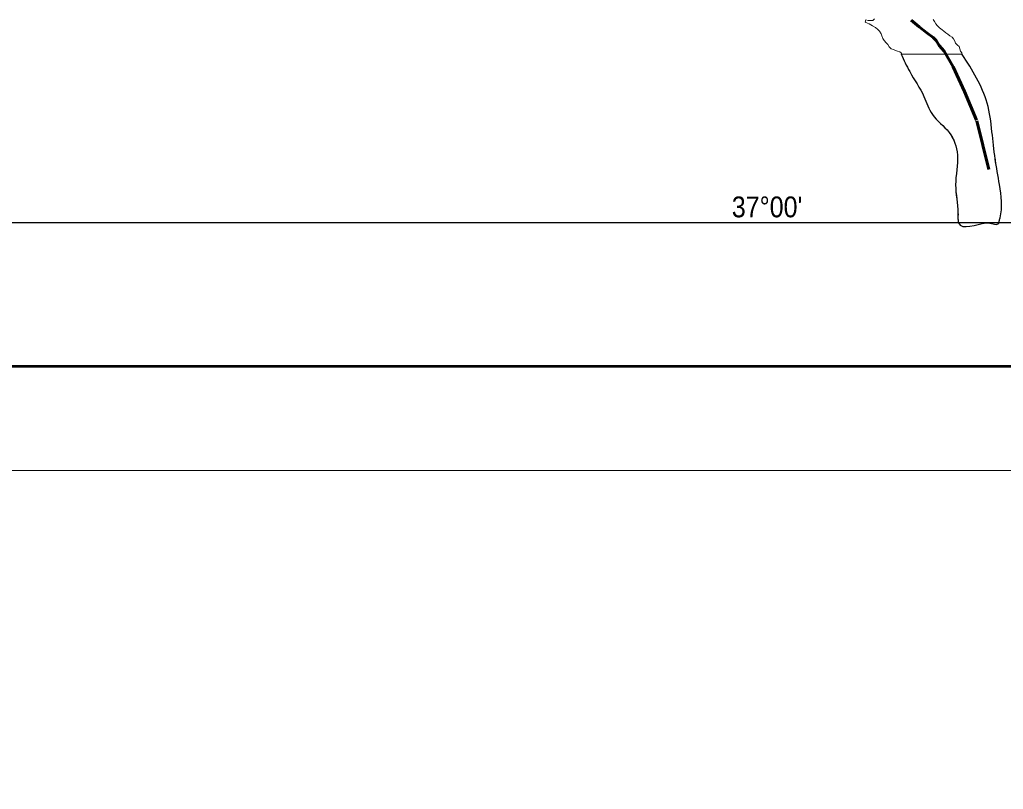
# Model space of a CAD drawing. Extents: x -1643653 to 4543381, y 1624270 to 13878484.
# Drawn here: x 701363 to 724990, y 8876229 to 8894722 of the extents above; entities that cross this region are included whole.
import ezdxf
from ezdxf.enums import TextEntityAlignment as Align

# ---------------------------------------------------------------- set-up
doc = ezdxf.new("R2010")
doc.units = 0
doc.header["$LTSCALE"] = 200
doc.linetypes.add('LONG_DASH_SHORT_DASH', pattern=[9.9, 6, -1.2, 1.5, -1.2])
for name, color, linetype, lineweight in [('1', 7, 'Continuous', 13), ('25', 7, 'Continuous', 13), ('3', 7, 'Continuous', 13), ('7', 7, 'LONG_DASH_SHORT_DASH', 60)]:
    doc.layers.add(name, color=color, linetype=linetype, lineweight=lineweight)
doc.layers.add('46', color=7, linetype='Continuous')

msp = doc.modelspace()

# ---------------------------------------------------------------- linework, layer by layer
at = {"layer": '1', "lineweight": 25}
msp.add_spline([(814781, 9009175.5), (814787.2, 9009173.4), (814796.9, 9009173.4), (814799.4, 9009172.4), (814805.1, 9009174.5), (814805.6, 9009176.5), (814811.7, 9009179.5), (814811.7, 9009179.5), (814801.5, 9009181), (814790.7, 9009181.5), (814784.1, 9009183.1), (814777.4, 9009185.1), (814778.4, 9009175.5)], degree=3, dxfattribs=at)
at = {"layer": '25', "lineweight": 25}
msp.add_line((724002.8, 8893886.5), (722537.3, 8893896.5), dxfattribs=at)
msp.add_line((724002.8, 8893886.5), (722537.3, 8893896.5), dxfattribs=at)
at = {"layer": '25'}
for points in [[(722073.4, 8894336.8), (722053.4, 8894382.8), (722013.2, 8894449.3), (721972.7, 8894485.2), (721917.1, 8894531.4), (721846.2, 8894572.6), (721770.2, 8894618.9), (721724.6, 8894639.6), (721673.9, 8894665.4), (721689.5, 8894716.2), (721745.3, 8894700.6), (721801.3, 8894700.2), (721852.2, 8894705), (721893.1, 8894740.4)], [(723301.9, 8894726.3), (723337.1, 8894675.1), (723367.3, 8894624), (723402.6, 8894583), (723453.1, 8894526.7), (723518.8, 8894475.3), (723564.4, 8894449.5), (723609.9, 8894408.5), (723655.5, 8894372.5), (723706.1, 8894336.6), (723761.8, 8894305.6), (723797.1, 8894259.6), (723827.3, 8894208.4), (723842.2, 8894157.4), (723887.6, 8894111.3), (723928.1, 8894075.3), (723948, 8894019.2)], [(722537.3, 8893896.5), (722543.5, 8893916.1), (722503.1, 8893952.1), (722447.2, 8893962.6), (722401.6, 8893983.3), (722350.9, 8894004), (722295.1, 8894024.7), (722244.5, 8894065.8), (722214.3, 8894122), (722174, 8894168.1), (722128.6, 8894224.4), (722098.4, 8894270.5), (722073.4, 8894336.8)], [(723948, 8894019.2), (723962.9, 8893968.2), (723993.2, 8893927.2), (724002.8, 8893886.5), (722537.3, 8893896.5)]]:
    msp.add_lwpolyline(points, dxfattribs=at)
at = {"layer": '25', "lineweight": 25}
for points in [[(722537.3, 8893896.5), (722740.6, 8893475.5), (723084.4, 8892873.8), (723285, 8892444), (723686.1, 8892014.3), (723886.7, 8891469.9), (723843.7, 8890753.6), (723901, 8890080.3), (723900.8, 8889934.8), (723915.3, 8889836.7), (724574.3, 8889836.7), (724631.6, 8889836.7), (724883.2, 8889836.5), (724893.2, 8889883.7), (724911.8, 8889958.1), (724898, 8890758.3), (724794.3, 8891380.3), (724717.6, 8892028.6), (724603, 8892716.2), (724002.8, 8893886.5)], [(722537.3, 8893896.5), (722740.6, 8893475.5), (723084.4, 8892873.8), (723285, 8892444), (723686.1, 8892014.3), (723886.7, 8891469.9), (723843.7, 8890753.6), (723901, 8890080.3), (723901.3, 8889998.4)], [(724811.6, 8891262.3), (724794.3, 8891380.3), (724717.6, 8892028.6), (724603, 8892716.2), (724002.8, 8893886.5)]]:
    msp.add_spline(points, degree=3, dxfattribs=at)
at = {"layer": '3'}
msp.add_lwpolyline([(842807.3, 9032387.8), (842807.3, 8883887.8), (553961.7, 8883887.8), (553961.7, 9032387.8)], close=True, dxfattribs=at)
msp.add_lwpolyline([(842807.3, 9032387.8), (842807.3, 8883887.8), (553961.7, 8883887.8), (553961.7, 9032387.8)], close=True, dxfattribs=at)
at = {"layer": '3', "lineweight": 53}
msp.add_lwpolyline([(840307.3, 9029887.8), (840307.3, 8886387.8), (560211.7, 8886387.8), (560211.7, 9029887.8)], close=True, dxfattribs=at)
msp.add_lwpolyline([(840307.3, 9029887.8), (840307.3, 8886387.8), (560211.7, 8886387.8), (560211.7, 9029887.8)], close=True, dxfattribs=at)
at = {"layer": '3', "lineweight": 25}
msp.add_lwpolyline([(563033.9, 9026438.8), (793061.1, 9026438.8), (793495.6, 8889836.8), (563468.3, 8889836.8)], close=True, dxfattribs=at)
at = {"layer": '7'}
msp.add_lwpolyline([(724638.9, 8891123.6), (724349.6, 8892305.9), (724059.6, 8892992.2), (723788.9, 8893591.5), (723566.6, 8893968.5), (723450.6, 8894103.8), (723373.3, 8894219.2), (723307.3, 8894290.7), (723154.9, 8894408.1), (722972, 8894546), (722773.8, 8894710.7)], dxfattribs=at)

# ---------------------------------------------------------------- texts
at = {"layer": '46', "width": 0.9}
msp.add_text("37°00'", height=500, dxfattribs=at).set_placement((719315, 8889973.1), align=Align.CENTER)

doc.saveas('drawing.dxf')
